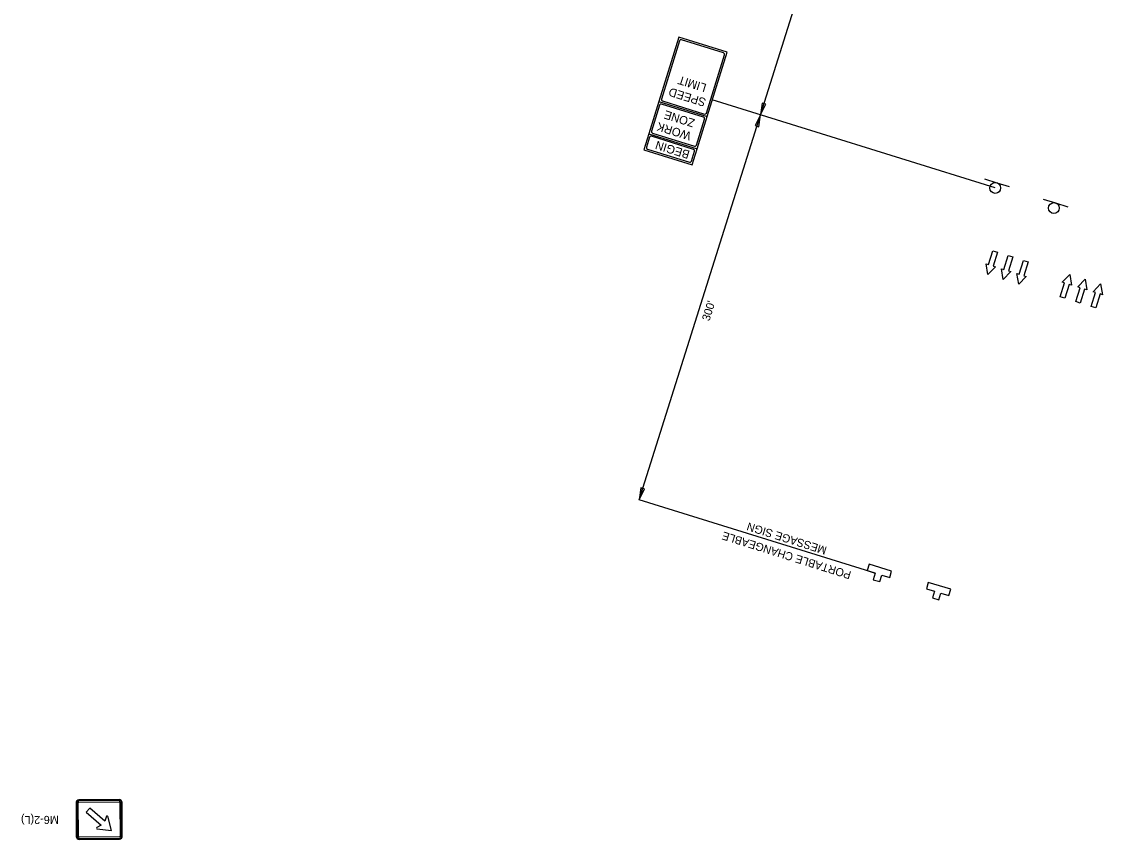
# Model space of a CAD drawing. Extents: x 2135767 to 2151731, y 141839 to 175894.
# Drawn here: x 2150477 to 2151280, y 148215 to 148823 of the extents above; entities that cross this region are included whole.
import ezdxf

# ---------------------------------------------------------------- set-up
doc = ezdxf.new("R2010")
doc.units = 0
for name, color, linetype in [('Default', 7, 'Continuous'), ('PR_Dimensions', 7, 'Continuous'), ('PR_Dimensions_Phase', 7, 'Continuous'), ('PR_Phasing_Detour_1', 7, 'Continuous'), ('Pr_Traffic_Arrows_Phase_1', 7, 'Continuous'), ('PR_Traffic_Control_Devices_Temp', 7, 'Continuous'), ('PR_Traffic_Sign_Temp', 7, 'Continuous'), ('PR_Txt', 7, 'Continuous')]:
    doc.layers.add(name, color=color, linetype=linetype)

# ---------------------------------------------------------------- blocks, each defined once
blk = doc.blocks.new('Arrowhd')
at = {"layer": 'Default'}
blk.add_lwpolyline([(0.318, -0.053), (0.318, 0.053), (0, 0)], close=True, dxfattribs=at)
blk = doc.blocks.new('PR-TCSIGN_rev')
at = {"layer": 'Default'}
blk.add_lwpolyline([(-5.47, 0), (-1.58, 0), (-1.58, -3.22), (1.58, -3.22), (1.58, 0), (5.47, 0), (5.47, 3.06), (-5.47, 3.06)], close=True, dxfattribs=at)
blk.add_lwpolyline([(1.58, 0), (5.47, 0), (5.47, 3.06), (-5.47, 3.06), (-5.47, 0), (-1.58, 0), (-1.58, -3.22), (1.58, -3.22), (1.58, 0)], dxfattribs=at)
blk = doc.blocks.new('R2-1E')
at = {"layer": 'Default'}
for p, q in [((7.62, 10.16), (0, 10.16)), ((0, 10.16), (0, 0)), ((7.14, 9.91), (0.48, 9.91)), ((7.62, 0), (7.62, 10.16)), ((0.25, 9.68), (0.25, 0.48)), ((7.37, 0.48), (7.37, 9.68)), ((0, 0), (7.62, 0)), ((0.48, 0.25), (7.14, 0.25))]:
    blk.add_line(p, q, dxfattribs=at)
for centre, start, end in [((0.48, 9.68), 90, 180), ((7.14, 9.68), 0, 90), ((0.48, 0.48), 180, 270), ((7.14, 0.48), 270, 0)]:
    blk.add_arc(centre, 0.222, start, end, dxfattribs=at)
for s, p in [('SPEED', (0.85, 7.62)), ('LIMIT', (1.44, 5.5))]:
    blk.add_text(s, height=1.27, dxfattribs=at).set_placement(p)
blk = doc.blocks.new('CS-14E')
at = {"layer": 'Default'}
for p, q in [((7.62, 2.54), (0, 2.54)), ((0, 2.54), (0, -2.54)), ((0.25, 2.06), (0.25, -2.06)), ((7.14, 2.29), (0.48, 2.29)), ((7.37, -2.06), (7.37, 2.06)), ((7.62, -2.54), (7.62, 2.54)), ((7.62, -2.54), (0, -2.54)), ((0.48, -2.29), (7.14, -2.29))]:
    blk.add_line(p, q, dxfattribs=at)
for centre, start, end in [((0.48, 2.06), 90, 180), ((7.14, 2.06), 0, 90), ((0.48, -2.06), 180, 270), ((7.14, -2.06), 270, 0)]:
    blk.add_arc(centre, 0.222, start, end, dxfattribs=at)
for s, p in [('WORK', (1.48, 0.44)), ('ZONE', (1.53, -1.6))]:
    blk.add_text(s, height=1.27, dxfattribs=at).set_placement(p)
blk = doc.blocks.new('CS-13E')
at = {"layer": 'Default'}
for p, q in [((0, 2.54), (0, 0)), ((7.62, 2.54), (0, 2.54)), ((0.25, 2.06), (0.25, 0.48)), ((7.14, 2.29), (0.48, 2.29)), ((7.37, 0.48), (7.37, 2.06)), ((7.62, 0), (7.62, 2.54)), ((7.62, 0), (0, 0)), ((0.48, 0.25), (7.14, 0.25))]:
    blk.add_line(p, q, dxfattribs=at)
for centre, start, end in [((0.48, 2.06), 90, 180), ((7.14, 2.06), 0, 90), ((0.48, 0.48), 180, 270), ((7.14, 0.48), 270, 0)]:
    blk.add_arc(centre, 0.222, start, end, dxfattribs=at)
blk.add_text('BEGIN', height=1.27, dxfattribs=at).set_placement((0.85, 0.64))

msp = doc.modelspace()

# ---------------------------------------------------------------- linework, layer by layer
at = {"layer": 'PR_Dimensions'}
msp.add_line((2150936.02, 148467.69), (2151108.72, 149015.64), dxfattribs=at)
at = {"layer": 'PR_Dimensions_Phase'}
for p, q in [((2151200.5, 148699.2), (2150990.29, 148764.56)), ((2151111.31, 148413.2), (2150936.02, 148467.69))]:
    msp.add_line(p, q, dxfattribs=at)
at = {"layer": 'PR_Phasing_Detour_1'}
for p, q in [((2150517.74, 148242.51), (2150517.95, 148217.53)), ((2150518.35, 148242.51), (2150518.56, 148217.54)), ((2150518.35, 148242.51), (2150518.56, 148217.54)), ((2150519.57, 148217.55), (2150519.37, 148242.52)), ((2150519.57, 148217.55), (2150519.37, 148242.52)), ((2150549.75, 148244.93), (2150519.89, 148244.69)), ((2150549.75, 148244.32), (2150519.9, 148244.08)), ((2150549.75, 148244.32), (2150519.9, 148244.08)), ((2150519.9, 148243.06), (2150549.76, 148243.3)), ((2150519.9, 148243.06), (2150549.76, 148243.3)), ((2150550.3, 148242.77), (2150550.5, 148217.8)), ((2150550.3, 148242.77), (2150550.5, 148217.8)), ((2150551.52, 148217.8), (2150551.32, 148242.78)), ((2150551.52, 148217.8), (2150551.32, 148242.78)), ((2150552.13, 148217.81), (2150551.93, 148242.78)), ((2150544.16, 148221.99), (2150541.41, 148232.61)), ((2150533.25, 148223.16), (2150544.16, 148221.99)), ((2150549.97, 148217.26), (2150520.11, 148217.02)), ((2150549.97, 148217.26), (2150520.11, 148217.02)), ((2150520.12, 148216), (2150549.98, 148216.24)), ((2150520.12, 148216), (2150549.98, 148216.24)), ((2150520.13, 148215.39), (2150549.99, 148215.63))]:
    msp.add_line(p, q, dxfattribs=at)
for points in [[(2150540.44, 148232.54), (2150539.22, 148229.01), (2150528, 148238.69), (2150525.28, 148235.54), (2150536.5, 148225.85), (2150533.18, 148224.14)], [(2150540.44, 148232.54), (2150539.22, 148229.01), (2150528, 148238.69), (2150525.28, 148235.54), (2150536.5, 148225.85), (2150533.18, 148224.14)], [(2150544.16, 148221.99), (2150541.41, 148232.61)], [(2150533.25, 148223.16), (2150544.16, 148221.99)]]:
    msp.add_lwpolyline(points, dxfattribs=at)
for centre, radius, start, end in [((2150519.91, 148242.53), 2.16, 90.46107, 180.46107), ((2150519.91, 148242.53), 1.55, 90.46107, 180.46107), ((2150519.91, 148242.53), 1.55, 90.46107, 180.46107), ((2150519.91, 148242.53), 0.537, 90.46107, 180.46107), ((2150519.91, 148242.53), 0.537, 90.46107, 180.46107), ((2150549.77, 148242.77), 2.16, 0.46107, 90.46107), ((2150549.77, 148242.77), 1.55, 0.46107, 90.46107), ((2150549.77, 148242.77), 1.55, 0.46107, 90.46107), ((2150549.77, 148242.77), 0.537, 0.46107, 90.46107), ((2150549.77, 148242.77), 0.537, 0.46107, 90.46107), ((2150540.96, 148232.09), 0.694, 49.20236, 139.20236), ((2150540.96, 148232.09), 0.694, 49.20236, 139.20236), ((2150533.71, 148223.68), 0.694, 139.20236, 229.20236), ((2150533.71, 148223.68), 0.694, 139.20236, 229.20236), ((2150549.97, 148217.79), 0.537, 270.46107, 0.46107), ((2150549.97, 148217.79), 0.537, 270.46107, 0.46107), ((2150549.97, 148217.79), 1.55, 270.46107, 0.46107), ((2150549.97, 148217.79), 1.55, 270.46107, 0.46107), ((2150549.97, 148217.79), 2.16, 270.46107, 0.46107), ((2150520.11, 148217.55), 2.16, 180.46107, 270.46107), ((2150520.11, 148217.55), 1.55, 180.46107, 270.46107), ((2150520.11, 148217.55), 1.55, 180.46107, 270.46107), ((2150520.11, 148217.55), 0.537, 180.46107, 270.46107), ((2150520.11, 148217.55), 0.537, 180.46107, 270.46107)]:
    msp.add_arc(centre, radius, start, end, dxfattribs=at)
at = {"layer": 'Pr_Traffic_Arrows_Phase_1'}
for p, q in [((2151195.46, 148642.27), (2151198.68, 148652.58)), ((2151198.68, 148652.58), (2151202.12, 148651.51)), ((2151202.12, 148651.51), (2151198.9, 148641.2)), ((2151206.92, 148638.7), (2151210.14, 148649.01)), ((2151210.14, 148649.01), (2151213.57, 148647.93)), ((2151213.57, 148647.93), (2151210.35, 148637.62)), ((2151218.37, 148635.12), (2151221.59, 148645.43)), ((2151221.59, 148645.43), (2151225.03, 148644.36)), ((2151225.03, 148644.36), (2151221.81, 148634.05)), ((2151195.04, 148634.86), (2151193.74, 148642.81)), ((2151193.74, 148642.81), (2151195.46, 148642.27)), ((2151200.62, 148640.66), (2151195.04, 148634.86)), ((2151198.9, 148641.2), (2151200.62, 148640.66)), ((2151206.49, 148631.29), (2151205.2, 148639.23)), ((2151205.2, 148639.23), (2151206.92, 148638.7)), ((2151212.07, 148637.09), (2151206.49, 148631.29)), ((2151210.35, 148637.62), (2151212.07, 148637.09)), ((2151217.94, 148627.71), (2151216.65, 148635.66)), ((2151216.65, 148635.66), (2151218.37, 148635.12)), ((2151223.53, 148633.51), (2151217.94, 148627.71)), ((2151221.81, 148634.05), (2151223.53, 148633.51)), ((2151248.8, 148618.37), (2151252.01, 148628.68)), ((2151250.29, 148629.22), (2151255.87, 148635.02)), ((2151252.01, 148628.68), (2151250.29, 148629.22)), ((2151255.45, 148627.61), (2151252.23, 148617.3)), ((2151257.16, 148627.07), (2151255.45, 148627.61)), ((2151255.87, 148635.02), (2151257.16, 148627.07)), ((2151261.75, 148625.65), (2151267.33, 148631.45)), ((2151267.33, 148631.45), (2151268.62, 148623.5)), ((2151273.2, 148622.08), (2151278.78, 148627.88)), ((2151278.78, 148627.88), (2151280.08, 148619.93)), ((2151260.25, 148614.8), (2151263.47, 148625.11)), ((2151263.47, 148625.11), (2151261.75, 148625.65)), ((2151266.9, 148624.04), (2151263.69, 148613.73)), ((2151268.62, 148623.5), (2151266.9, 148624.04)), ((2151271.71, 148611.23), (2151274.92, 148621.54)), ((2151274.92, 148621.54), (2151273.2, 148622.08)), ((2151278.36, 148620.47), (2151275.15, 148610.16)), ((2151280.08, 148619.93), (2151278.36, 148620.47)), ((2151252.23, 148617.3), (2151248.8, 148618.37)), ((2151263.69, 148613.73), (2151260.25, 148614.8)), ((2151275.15, 148610.16), (2151271.71, 148611.23))]:
    msp.add_line(p, q, dxfattribs=at)
at = {"layer": 'PR_Traffic_Sign_Temp'}
for p, q in [((2151192.45, 148705.86), (2151201.67, 148703.02)), ((2151201.67, 148703.02), (2151210.9, 148700.19)), ((2151235.99, 148690.93), (2151245.21, 148688.09)), ((2151245.21, 148688.09), (2151254.44, 148685.26))]:
    msp.add_line(p, q, dxfattribs=at)
for centre in [(2151200.5, 148699.2), (2151244.04, 148684.27)]:
    msp.add_circle(centre, 4, dxfattribs=at)

# ---------------------------------------------------------------- block references
at = {"layer": 'PR_Dimensions', "xscale": 27.559000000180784, "yscale": 27.559000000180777}
for p, rotation in [((2151026.14, 148753.39), 72.57227732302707), ((2151026.08, 148753.43), -107.4277226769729), ((2150936.02, 148467.69), 72.57227732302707)]:
    msp.add_blockref('Arrowhd', p, dxfattribs=dict(at, rotation=rotation))
at = {"layer": 'PR_Traffic_Control_Devices_Temp'}
for name, p, xscale, yscale, rotation in [('R2-1E', (2151001.29, 148799.95), 4.92125000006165, 4.92125000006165, 162.72812962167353), ('CS-14E', (2150982.73, 148740.27), 4.921249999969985, 4.9212499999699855, 162.7281296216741), ('CS-13E', (2150979.02, 148728.34), 4.921249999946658, 4.92124999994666, 162.72812961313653), ('PR-TCSIGN_rev', (2151113.73, 148412.46), 1.5993550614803, 1.5993550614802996, -16.802196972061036), ('PR-TCSIGN_rev', (2151157.71, 148398.97), 1.5993550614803, 1.5993550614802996, -16.802196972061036)]:
    msp.add_blockref(name, p, dxfattribs=dict(at, xscale=xscale, yscale=yscale, rotation=rotation))

# ---------------------------------------------------------------- texts
at = {"layer": 'PR_Phasing_Detour_1'}
msp.add_text('M6-2(L)', height=6, rotation=180.46107, dxfattribs=at).set_placement((2150504.92, 148232.91))
at = {"layer": 'PR_Txt'}
for s, rotation, p in [("300'", 72.57228, (2150988.18, 148599.95)), ('MESSAGE SIGN', 162.57228, (2151075.86, 148432.46)), ('PORTABLE CHANGEABLE', 162.57228, (2151093.98, 148414.19))]:
    msp.add_text(s, height=6, rotation=rotation, dxfattribs=at).set_placement(p)

doc.saveas('drawing.dxf')
